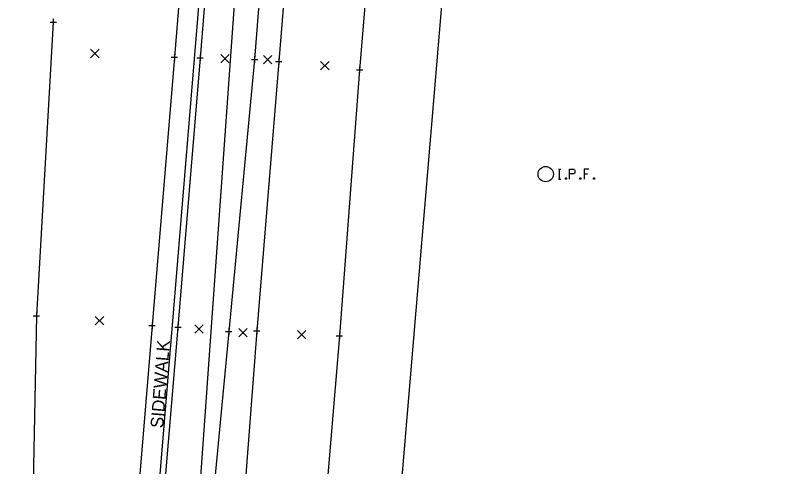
# Model space of a CAD drawing. Extents: x 1380440 to 1381945, y 468756 to 470369.
# Drawn here: x 1381544.2 to 1381665.6, y 469907.6 to 469978.3 of the extents above; entities that cross this region are included whole.
import ezdxf

# ---------------------------------------------------------------- set-up
doc = ezdxf.new("R2010")
doc.units = 0
for name, color, linetype in [('DR_P_Headwall', 7, 'Continuous'), ('GE_P_Driveway_CL', 7, 'Continuous'), ('PM_X_CL_Double_Solid', 7, 'Continuous'), ('PV_P_Curb', 7, 'Continuous'), ('RW_P_Esmt_TMP', 7, 'Continuous'), ('SC_Scratch1', 7, 'Continuous'), ('SC_Shading1', 7, 'Continuous'), ('SH_Named_Boundary', 7, 'Continuous'), ('UT_X_Gas', 7, 'Continuous'), ('UT_X_Overhead_Combined', 7, 'Continuous'), ('UT_X_Water', 7, 'Continuous'), ('X-SUBDIVISION', 7, 'Continuous')]:
    doc.layers.add(name, color=color, linetype=linetype)

msp = doc.modelspace()

# ---------------------------------------------------------------- linework, layer by layer
at = {"layer": 'DR_P_Headwall'}
for points in [[(1381595.25, 470241), (1381595.01, 470239.38), (1381594.79, 470235.56), (1381591.94, 470203.13), (1381590.15, 470180.15), (1381585.84, 470126.11), (1381581.45, 470072.84), (1381577.22, 470021.47), (1381573.16, 469971.68), (1381569.7, 469929.43), (1381565.6, 469880.89), (1381564.41, 469867), (1381562.95, 469848.39), (1381561.9, 469840.88)], [(1381542.56, 470237.64), (1381568.34, 470236.69), (1381578.51, 470236.26), (1381584.49, 470236.02), (1381590.64, 470235.62), (1381587.95, 470203.42), (1381586.62, 470180.46), (1381581.93, 470126.46), (1381577.65, 470073.24), (1381573.2, 470021.54), (1381569.15, 469971.74), (1381565.64, 469929.65), (1381561.64, 469881.16), (1381560.46, 469867.32), (1381559.27, 469848.71), (1381558.35, 469840.14)]]:
    msp.add_lwpolyline(points, dxfattribs=at)
at = {"layer": 'GE_P_Driveway_CL'}
for p, q in [((1381555.99, 469971.67), (1381557.33, 469973.01)), ((1381555.99, 469973.01), (1381557.33, 469971.67)), ((1381576.42, 469970.87), (1381577.75, 469972.2)), ((1381576.42, 469972.2), (1381577.75, 469970.87)), ((1381583.09, 469970.7), (1381584.43, 469972.04)), ((1381583.09, 469972.04), (1381584.43, 469970.7)), ((1381592.06, 469969.78), (1381593.39, 469971.11)), ((1381592.06, 469971.11), (1381593.39, 469969.78)), ((1381556.74, 469929.76), (1381558.07, 469931.1)), ((1381556.74, 469931.1), (1381558.07, 469929.76)), ((1381572.32, 469928.46), (1381573.66, 469929.79)), ((1381572.32, 469929.79), (1381573.66, 469928.46)), ((1381579.24, 469927.88), (1381580.57, 469929.21)), ((1381579.24, 469929.21), (1381580.57, 469927.88)), ((1381588.43, 469927.56), (1381589.76, 469928.89)), ((1381588.43, 469928.89), (1381589.76, 469927.56))]:
    msp.add_line(p, q, dxfattribs=at)
at = {"layer": 'PM_X_CL_Double_Solid'}
msp.add_lwpolyline([(1381618.76, 470220.14), (1381616.92, 470200.19), (1381615.1, 470178.83), (1381610.95, 470124.78), (1381606.49, 470071.23), (1381602.26, 470019.36), (1381598.18, 469969.8), (1381595.01, 469928.06), (1381590.91, 469878.81), (1381589.36, 469859.11), (1381585.99, 469815.58), (1381581.29, 469760.78), (1381580.3, 469747.86), (1381578.72, 469729.45), (1381576.78, 469708.95), (1381575.29, 469689.79), (1381572.76, 469657.56), (1381569.36, 469615.7), (1381565.36, 469567.23), (1381561.16, 469537.52), (1381558.94, 469486.81), (1381555.39, 469442.03), (1381550.97, 469391.02)], dxfattribs=at)
at = {"layer": 'PV_P_Curb'}
msp.add_lwpolyline([(1381599.49, 470202.78), (1381597.12, 470179.51), (1381597.25, 470175.53), (1381597.2, 470175.03), (1381592.57, 470125.52), (1381589.1, 470072.43), (1381585.65, 470022.01), (1381581.71, 469971.4), (1381577.66, 469928.75), (1381573.1, 469880.44), (1381570.64, 469867.29)], dxfattribs=at)
at = {"layer": 'RW_P_Esmt_TMP'}
for points in [[(1381575.39, 470244.04), (1381576.99, 470244.17), (1381579.54, 470245.54), (1381580.63, 470247.96), (1381580.96, 470249.54), (1381591.47, 470243.59), (1381595.25, 470241), (1381599.72, 470235.67), (1381603.29, 470229.19), (1381604.88, 470222.31), (1381604.1, 470201.73), (1381602.36, 470179.43), (1381598.63, 470125.51), (1381593.59, 470071.89), (1381589.53, 470020.65), (1381585.49, 469971.09), (1381582.04, 469928.84), (1381578.38, 469880.28), (1381576.86, 469862.02), (1381576.83, 469860.71), (1381576.16, 469857.38), (1381571.59, 469847.12), (1381563.14, 469838.25)], [(1381550.16, 469977.26), (1381547.52, 469931.2), (1381546.52, 469881.36), (1381546.07, 469867.59), (1381545.21, 469852.93)]]:
    msp.add_lwpolyline(points, dxfattribs=at)
at = {"layer": 'SC_Scratch1'}
for points in [[(1381629.36, 469954.22), (1381629.71, 469954.22)], [(1381629.53, 469952.62), (1381629.53, 469954.22)], [(1381631.1, 469952.62), (1381631.1, 469954.22), (1381631.63, 469954.22), (1381631.68, 469954.21), (1381631.76, 469954.18), (1381631.79, 469954.16), (1381631.83, 469954.13), (1381631.87, 469954.07), (1381631.9, 469954.01), (1381631.92, 469953.91), (1381631.92, 469953.75), (1381631.91, 469953.7), (1381631.89, 469953.63), (1381631.85, 469953.54), (1381631.8, 469953.5), (1381631.77, 469953.48), (1381631.72, 469953.45), (1381631.63, 469953.44), (1381631.1, 469953.44)], [(1381634.11, 469954.22), (1381633.35, 469954.22), (1381633.35, 469952.62)], [(1381629.36, 469952.62), (1381629.71, 469952.62)], [(1381630.49, 469952.84), (1381630.55, 469952.84), (1381630.58, 469952.81), (1381630.61, 469952.76), (1381630.61, 469952.7), (1381630.58, 469952.65), (1381630.55, 469952.62), (1381630.49, 469952.62), (1381630.46, 469952.65), (1381630.43, 469952.7), (1381630.43, 469952.76), (1381630.46, 469952.81), (1381630.49, 469952.84)], [(1381632.74, 469952.84), (1381632.8, 469952.84), (1381632.83, 469952.81), (1381632.86, 469952.76), (1381632.86, 469952.7), (1381632.83, 469952.65), (1381632.8, 469952.62), (1381632.74, 469952.62), (1381632.71, 469952.65), (1381632.67, 469952.7), (1381632.67, 469952.76), (1381632.71, 469952.81), (1381632.74, 469952.84)], [(1381633.35, 469953.44), (1381633.89, 469953.44)], [(1381634.89, 469952.84), (1381634.94, 469952.84), (1381634.98, 469952.81), (1381635.01, 469952.76), (1381635.01, 469952.7), (1381634.98, 469952.65), (1381634.94, 469952.62), (1381634.89, 469952.62), (1381634.86, 469952.65), (1381634.82, 469952.7), (1381634.82, 469952.76), (1381634.86, 469952.81), (1381634.89, 469952.84)]]:
    msp.add_lwpolyline(points, dxfattribs=at)
msp.add_circle((1381627.34, 469953.42), 1.2, dxfattribs=at)
at = {"layer": 'SC_Shading1'}
msp.add_lwpolyline([(1381627.41, 470324.23), (1381625.02, 470294.42), (1381622.34, 470259.95), (1381618.76, 470220.14), (1381616.92, 470200.19), (1381615.1, 470178.83), (1381610.95, 470124.78), (1381606.49, 470071.23), (1381602.26, 470019.36), (1381598.18, 469969.8), (1381595.01, 469928.06), (1381590.91, 469878.81), (1381589.36, 469859.11), (1381585.99, 469815.58)], dxfattribs=at)
at = {"layer": 'SH_Named_Boundary'}
for p, q in [((1381549.66, 469977.26), (1381550.66, 469977.26)), ((1381550.16, 469977.76), (1381550.16, 469976.76)), ((1381550.16, 469977.26), (1381550.16, 469977.26)), ((1381568.65, 469971.74), (1381569.65, 469971.74)), ((1381569.15, 469972.24), (1381569.15, 469971.24)), ((1381569.15, 469971.74), (1381569.15, 469971.74)), ((1381573.16, 469972.18), (1381573.16, 469971.18)), ((1381581.71, 469971.9), (1381581.71, 469970.9)), ((1381572.66, 469971.68), (1381573.66, 469971.68)), ((1381573.16, 469971.68), (1381573.16, 469971.68)), ((1381581.21, 469971.4), (1381582.21, 469971.4)), ((1381581.71, 469971.4), (1381581.71, 469971.4)), ((1381584.99, 469971.09), (1381585.99, 469971.09)), ((1381585.49, 469971.59), (1381585.49, 469970.59)), ((1381585.49, 469971.09), (1381585.49, 469971.09)), ((1381597.68, 469969.8), (1381598.68, 469969.8)), ((1381598.18, 469970.3), (1381598.18, 469969.3)), ((1381598.18, 469969.8), (1381598.18, 469969.8)), ((1381547.52, 469931.7), (1381547.52, 469930.7)), ((1381547.02, 469931.2), (1381548.02, 469931.2)), ((1381547.52, 469931.2), (1381547.52, 469931.2)), ((1381565.14, 469929.65), (1381566.14, 469929.65)), ((1381565.64, 469930.15), (1381565.64, 469929.15)), ((1381565.64, 469929.65), (1381565.64, 469929.65)), ((1381569.2, 469929.43), (1381570.2, 469929.43)), ((1381569.7, 469929.93), (1381569.7, 469928.93)), ((1381569.7, 469929.43), (1381569.7, 469929.43)), ((1381577.66, 469929.25), (1381577.66, 469928.25)), ((1381582.04, 469929.34), (1381582.04, 469928.34)), ((1381577.16, 469928.75), (1381578.16, 469928.75)), ((1381577.66, 469928.75), (1381577.66, 469928.75)), ((1381581.54, 469928.84), (1381582.54, 469928.84)), ((1381582.04, 469928.84), (1381582.04, 469928.84)), ((1381594.51, 469928.06), (1381595.51, 469928.06)), ((1381595.01, 469928.56), (1381595.01, 469927.56)), ((1381595.01, 469928.06), (1381595.01, 469928.06))]:
    msp.add_line(p, q, dxfattribs=at)
at = {"layer": 'UT_X_Gas'}
msp.add_lwpolyline([(1381485.9, 468926.41), (1381594.27, 470237.89), (1380558, 470279.29)], dxfattribs=at)
at = {"layer": 'UT_X_Overhead_Combined'}
msp.add_lwpolyline([(1381540.8, 469054.26), (1381515.28, 469203.1), (1381529.17, 469390.12), (1381543.86, 469565.78), (1381559.77, 469757.41), (1381571.97, 469887.64), (1381581.26, 470018.2), (1381595.79, 470220.83), (1381665.56, 470247.4)], dxfattribs=at)
at = {"layer": 'UT_X_Water'}
msp.add_line((1381545.41, 469194.71), (1381630.26, 470209.69), dxfattribs=at)

# ---------------------------------------------------------------- texts
at = {"layer": 'X-SUBDIVISION'}
msp.add_text('SIDEWALK', height=2, rotation=85.521, dxfattribs=at).set_placement((1381567.38, 469913.52))

doc.saveas('drawing.dxf')
